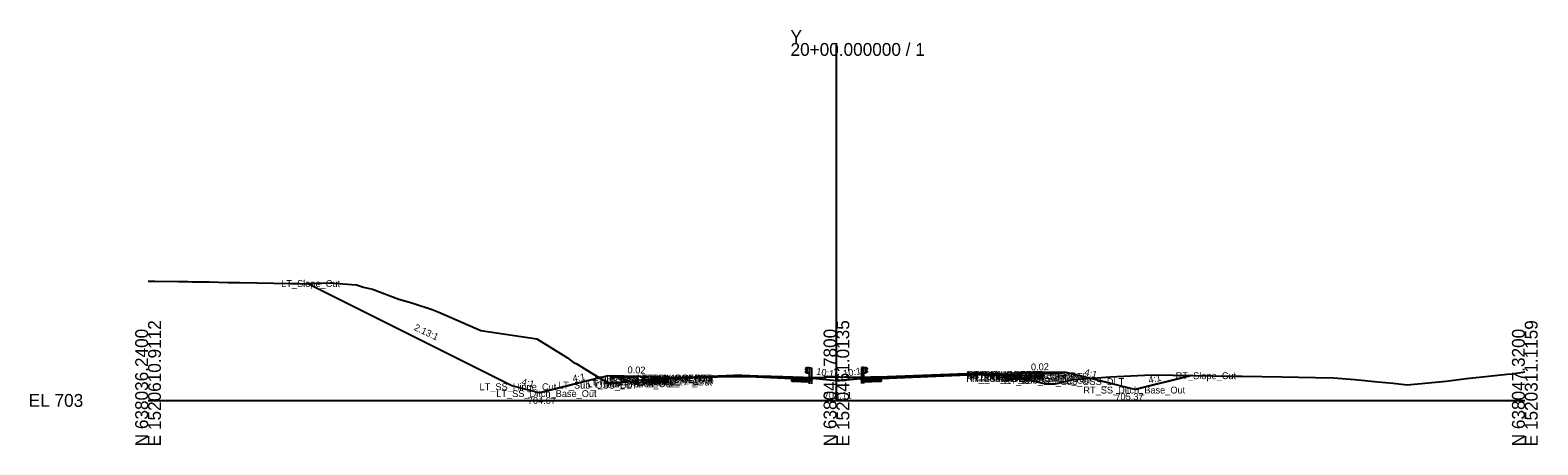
# Model space of a CAD drawing. Extents: x -26 to 303, y -10 to 5039.
# Drawn here: x -25.7 to 302.8, y 3490.3 to 3580.7 of the extents above; entities that cross this region are included whole.
import ezdxf

# ---------------------------------------------------------------- set-up
doc = ezdxf.new("R2010")
doc.units = 0
for name, color, linetype in [('Default', 7, 'Continuous'), ('Exist Cross Section Cell', 7, 'Continuous'), ('Exist XS Center Line Elevation Label', 7, 'Continuous'), ('Exist XS Ground Line', 7, 'Continuous'), ('Prop CMT Pvmt Course 1', 7, 'Continuous'), ('Prop CMT Pvmt Course 2', 7, 'Continuous'), ('Prop CMT Pvmt Course 3', 7, 'Continuous'), ('Prop CMT Pvmt Surface Shoulder', 7, 'Continuous'), ('Prop CMT Shld Paved Course 1', 7, 'Continuous'), ('Prop CMT Shld Paved Course 2', 7, 'Continuous'), ('Prop CMT Shld Paved Course 3', 7, 'Continuous'), ('Prop CMT Slope Grass', 7, 'Continuous'), ('Prop CMT Subgrade Earthwork', 7, 'Continuous'), ('Prop Conc 4in Sidewalk', 7, 'Continuous'), ('Prop XS Ditch Standard Text', 7, 'Continuous'), ('Prop XS Earthwork Shape', 7, 'Continuous'), ('Prop XS Side Slope Text', 7, 'Continuous'), ('Scratch_Level_0', 7, 'Continuous'), ('Typical Curb CELL', 7, 'Continuous'), ('Typical Guardrail CELL', 7, 'Continuous'), ('Typical Shoulder Slope Information CELL', 7, 'Continuous')]:
    doc.layers.add(name, color=color, linetype=linetype)

# ---------------------------------------------------------------- blocks, each defined once
blk = doc.blocks.new('2_6 CURB RIGHT')
at = {"layer": 'Typical Curb CELL'}
for p, q in [((0, -0.58), (0, 0)), ((0, 0), (1.75, -0.07)), ((2, 0.17), (2, 0.18)), ((2.5, 0.42), (2.24, 0.42)), ((2.31, 0.08), (2.33, -0.01)), ((2.46, 0.04), (2.31, 0.08)), ((2.33, -0.01), (2.46, 0.04)), ((2.5, -0.58), (2.5, 0.42)), ((2.5, -0.58), (0, -0.58)), ((0.26, -0.34), (0.35, -0.22)), ((0.38, -0.34), (0.26, -0.34)), ((0.35, -0.22), (0.38, -0.34)), ((1.03, -0.39), (1.09, -0.28)), ((1.19, -0.36), (1.03, -0.39)), ((1.09, -0.28), (1.19, -0.36)), ((1.51, -0.34), (1.6, -0.22)), ((1.63, -0.34), (1.51, -0.34)), ((1.6, -0.22), (1.63, -0.34)), ((2.27, -0.39), (2.34, -0.28)), ((2.44, -0.36), (2.27, -0.39)), ((2.34, -0.28), (2.44, -0.36))]:
    blk.add_line(p, q, dxfattribs=at)
for centre in [(2.27, 0.34), (2.43, 0.12), (2.49, 0.31), (0.01, -0.55), (0.02, -0.25), (0.03, -0.15), (0.07, -0.39), (0.09, -0.18), (0.17, -0.34), (0.2, -0.06), (0.22, -0.58), (0.3, -0.14), (0.34, -0.04), (0.38, -0.51), (0.49, -0.1), (0.52, -0.21), (0.59, -0.53), (0.67, -0.29), (0.69, -0.12), (0.7, -0.45), (0.71, -0.07), (0.76, -0.56), (0.79, -0.26), (0.93, -0.5), (0.97, -0.1), (1.09, -0.15), (1.11, -0.54), (1.26, -0.55), (1.27, -0.25), (1.28, -0.15), (1.32, -0.39), (1.34, -0.18), (1.42, -0.34), (1.45, -0.1), (1.47, -0.58), (1.54, -0.14), (1.63, -0.51), (1.74, -0.1), (1.77, -0.21), (1.84, -0.53), (1.92, -0.29), (1.94, -0.12), (1.95, -0.45), (1.96, -0.07), (2.01, -0.56), (2.04, -0.26), (2.18, -0.5), (2.22, -0.1), (2.34, -0.15), (2.35, -0.54)]:
    blk.add_circle(centre, 0.00802, dxfattribs=at)
for centre, start, end in [((1.76, 0.17), 267.6155, 0), ((2.24, 0.18), 90, 180)]:
    blk.add_arc(centre, 0.24, start, end, dxfattribs=at)

msp = doc.modelspace()

# ---------------------------------------------------------------- linework, layer by layer
at = {"layer": 'Exist Cross Section Cell'}
for p, q in [((150, 3500), (150, 3577.92)), ((0, 3500), (150, 3500)), ((150, 3500), (300, 3500))]:
    msp.add_line(p, q, dxfattribs=at)
at = {"layer": 'Exist XS Ground Line'}
msp.add_lwpolyline([(0, 3525.96), (0.71, 3525.96), (1.5, 3525.97), (6.64, 3525.95), (8.65, 3525.92), (9.66, 3525.87), (12.17, 3525.84), (12.72, 3525.84), (13.29, 3525.83), (17.41, 3525.74), (20.08, 3525.67), (31.09, 3525.46), (31.71, 3525.47), (32.03, 3525.48), (32.73, 3525.47), (34.16, 3525.45), (39.69, 3525.61), (40.1, 3525.62), (40.47, 3525.58), (45.43, 3525.17), (46.93, 3524.72), (48.94, 3524.24), (54.65, 3522.05), (57.49, 3521.25), (61.89, 3519.8), (63.34, 3519.21), (72.53, 3515.25), (84.74, 3513.45), (91.37, 3509.27), (92.73, 3508.27), (93.27, 3508.03), (100.24, 3503.74), (101.36, 3503.75), (101.73, 3503.79), (103.06, 3503.91), (110.58, 3504.76), (111.28, 3504.78), (111.58, 3504.79), (113.51, 3504.85), (114.1, 3504.89), (115.84, 3504.92), (118.35, 3505), (120.85, 3505.08), (121.65, 3505.1), (123.34, 3505.15), (125.84, 3505.22), (128.32, 3505.23), (130.49, 3505.24), (130.82, 3505.24), (132.91, 3505.23), (133.33, 3505.23), (133.78, 3505.23), (135.84, 3505.24), (136.32, 3505.24), (138.34, 3505.24), (142.72, 3505.05), (145, 3504.97), (147.38, 3505.03), (150, 3505.11), (150.67, 3505.13), (152.51, 3505.07), (157.46, 3505.12), (161.91, 3505.12), (162.77, 3505.13), (163.39, 3505.14), (165, 3505.2), (165.89, 3505.23), (166.72, 3505.27), (168.38, 3505.34), (170.18, 3505.41), (170.88, 3505.44), (172.76, 3505.51), (173.37, 3505.53), (173.87, 3505.57), (175.47, 3505.58), (175.86, 3505.59), (177.93, 3505.62), (178.35, 3505.63), (180.54, 3505.66), (181.16, 3505.67), (183.37, 3505.69), (184.8, 3505.69), (185.65, 3505.69), (187.49, 3505.51), (190.17, 3504.92), (195.52, 3503.64), (197.68, 3503.61), (198.38, 3503.75), (201.61, 3504.57), (206.92, 3504.93), (209.58, 3505.14), (217.2, 3505.53), (219.29, 3505.59), (231.77, 3505.35), (235.3, 3505.29), (238.43, 3505.26), (247.06, 3505.15), (254.39, 3505.02), (258.31, 3504.93), (262.96, 3504.54), (267.99, 3504.06), (271.3, 3503.77), (274.37, 3503.4), (282.83, 3504.2), (287.27, 3504.78), (292.12, 3505.28), (296.17, 3505.7), (297.31, 3505.81), (300, 3506.22)], dxfattribs=at)
at = {"layer": 'Prop CMT Pvmt Course 1'}
for points in [[(186.74, 3505.38), (186.74, 3505.63)], [(113.24, 3504.85), (113.24, 3504.6)], [(113.24, 3504.6), (113.25, 3504.6)], [(113.25, 3504.6), (113.25, 3504.85)], [(140.25, 3504.81), (140.25, 3505.06)], [(159.75, 3504.81), (159.75, 3505.06)]]:
    msp.add_lwpolyline(points, dxfattribs=at)
at = {"layer": 'Prop CMT Pvmt Course 2'}
for points in [[(113.25, 3504.6), (113.24, 3504.6)], [(113.24, 3504.6), (113.24, 3504.35)], [(113.24, 3504.35), (113.25, 3504.35)], [(113.25, 3504.35), (113.25, 3504.6)], [(140.25, 3504.56), (140.25, 3504.81)], [(159.75, 3504.56), (159.75, 3504.81)]]:
    msp.add_lwpolyline(points, dxfattribs=at)
at = {"layer": 'Prop CMT Pvmt Course 3'}
for points in [[(113.25, 3504.35), (113.24, 3504.35)], [(113.24, 3504.35), (113.24, 3503.98)], [(113.24, 3503.98), (113.25, 3503.98)], [(113.25, 3503.98), (113.25, 3504.35)], [(140.25, 3504.19), (140.25, 3504.56)], [(140.26, 3504.19), (140.25, 3504.19)], [(159.74, 3504.19), (159.75, 3504.19)], [(159.75, 3504.19), (159.75, 3504.56)]]:
    msp.add_lwpolyline(points, dxfattribs=at)
at = {"layer": 'Prop CMT Pvmt Surface Shoulder'}
for points in [[(129.39, 3505.5), (112.24, 3504.81)], [(129.39, 3505.5), (143.25, 3504.94)], [(180.3, 3505.88), (156.75, 3504.94)], [(180.3, 3505.88), (187.75, 3505.59)]]:
    msp.add_lwpolyline(points, dxfattribs=at)
at = {"layer": 'Prop CMT Shld Paved Course 1'}
for p, q in [((176.3, 3505.79), (187.74, 3505.34)), ((129.39, 3505.25), (113.25, 3504.6)), ((129.39, 3505.25), (140.25, 3504.81))]:
    msp.add_line(p, q, dxfattribs=at)
for points in [[(159.77, 3504.81), (180.3, 3505.63)], [(112.24, 3504.56), (113.25, 3504.6)], [(113.24, 3504.6), (113.24, 3504.85)], [(187.75, 3505.34), (186.74, 3505.38)]]:
    msp.add_lwpolyline(points, dxfattribs=at)
at = {"layer": 'Prop CMT Shld Paved Course 2'}
for p, q in [((143.77, 3504.42), (143.51, 3504.68)), ((156.23, 3504.42), (156.49, 3504.68))]:
    msp.add_line(p, q, dxfattribs=at)
for points in [[(113.25, 3504.6), (112.24, 3504.56)], [(112.24, 3504.31), (113.25, 3504.35)], [(113.24, 3504.35), (113.24, 3504.6)], [(140.25, 3504.81), (143.51, 3504.68)], [(143.77, 3504.42), (140.25, 3504.56)], [(156.23, 3504.42), (159.75, 3504.56)], [(159.75, 3504.81), (156.49, 3504.68)], [(186.74, 3505.38), (187.75, 3505.34)], [(187.75, 3505.09), (186.74, 3505.13)]]:
    msp.add_lwpolyline(points, dxfattribs=at)
at = {"layer": 'Prop CMT Shld Paved Course 3'}
for p, q in [((109.24, 3504.23), (108.81, 3503.8)), ((109.74, 3504.23), (109.24, 3504.23)), ((144.16, 3504.03), (143.77, 3504.42)), ((155.84, 3504.03), (156.23, 3504.42)), ((190.25, 3505), (190.75, 3505)), ((190.75, 3505), (191.18, 3504.57))]:
    msp.add_line(p, q, dxfattribs=at)
for points in [[(108.81, 3503.8), (113.25, 3503.98)], [(113.25, 3504.35), (112.24, 3504.31)], [(113.24, 3503.98), (113.24, 3504.35)], [(140.25, 3504.56), (143.77, 3504.42)], [(144.16, 3504.03), (140.25, 3504.19)], [(155.84, 3504.03), (159.75, 3504.19)], [(159.75, 3504.56), (156.23, 3504.42)], [(186.74, 3505.13), (187.75, 3505.09)], [(191.18, 3504.57), (186.74, 3504.75)]]:
    msp.add_lwpolyline(points, dxfattribs=at)
at = {"layer": 'Prop CMT Slope Grass'}
for p, q in [((199.75, 3506.19), (190.25, 3506)), ((215.03, 3502.37), (199.75, 3506.19)), ((85.24, 3501.67), (100.24, 3505.42)), ((100.24, 3505.42), (109.74, 3505.23)), ((150, 3504.27), (143.25, 3504.94)), ((150, 3504.27), (156.75, 3504.94)), ((215.03, 3502.37), (227.29, 3505.44))]:
    msp.add_line(p, q, dxfattribs=at)
msp.add_lwpolyline([(85.24, 3501.67), (79.24, 3503.17), (34.65, 3525.46)], dxfattribs=at)
at = {"layer": 'Prop CMT Subgrade Earthwork'}
for p, q in [((186.74, 3504.75), (186.74, 3505.63)), ((187.75, 3505), (187.75, 3505.59)), ((190.25, 3506), (190.25, 3505)), ((191.18, 3504.57), (192.65, 3506.05)), ((108.81, 3503.8), (107.34, 3505.27)), ((109.74, 3505.23), (109.74, 3504.23)), ((109.74, 3504.23), (112.24, 3504.23)), ((112.24, 3504.23), (112.24, 3504.81)), ((113.25, 3503.98), (113.25, 3504.85)), ((140.25, 3505.06), (140.25, 3504.19)), ((159.75, 3505.06), (159.75, 3504.19)), ((190.25, 3505), (187.75, 3505))]:
    msp.add_line(p, q, dxfattribs=at)
for points in [[(113.25, 3503.98), (108.81, 3503.8)], [(140.25, 3505.06), (140.25, 3504.19), (140.26, 3504.19)], [(140.25, 3504.19), (144.16, 3504.03)], [(144.16, 3504.03), (144.91, 3504.78)], [(155.84, 3504.03), (155.09, 3504.78)], [(159.75, 3504.19), (155.84, 3504.03)], [(159.75, 3505.06), (159.75, 3504.19), (159.74, 3504.19)], [(186.74, 3504.75), (191.18, 3504.57)]]:
    msp.add_lwpolyline(points, dxfattribs=at)
at = {"layer": 'Prop Conc 4in Sidewalk'}
for p, q in [((194.25, 3506.08), (194.25, 3505.75)), ((199.25, 3505.85), (194.25, 3505.75)), ((199.25, 3506.18), (199.25, 3505.85)), ((100.74, 3505.41), (100.74, 3505.07)), ((100.74, 3505.07), (105.74, 3504.97)), ((105.74, 3505.31), (105.74, 3504.97))]:
    msp.add_line(p, q, dxfattribs=at)
at = {"layer": 'Prop XS Earthwork Shape'}
for points in [[(40.1, 3525.62), (40.47, 3525.58), (45.43, 3525.17), (46.93, 3524.72), (48.94, 3524.24), (54.65, 3522.05), (57.49, 3521.25), (61.89, 3519.8), (63.34, 3519.21), (72.53, 3515.25), (84.74, 3513.45), (91.37, 3509.27), (92.73, 3508.27), (93.27, 3508.03), (98.3, 3504.93), (85.24, 3501.67), (79.24, 3503.17), (34.65, 3525.46), (39.69, 3525.61)], [(129.39, 3505.5), (135.81, 3505.24), (133.78, 3505.23), (133.33, 3505.23), (132.91, 3505.23), (130.82, 3505.24), (130.49, 3505.24), (128.32, 3505.23), (125.84, 3505.22), (123.34, 3505.15), (121.65, 3505.1), (120.85, 3505.08), (118.35, 3505), (115.84, 3504.92), (114.16, 3504.89)], [(183.37, 3505.69), (184.8, 3505.69), (185.2, 3505.69), (180.3, 3505.88), (161.15, 3505.12), (161.91, 3505.12), (162.77, 3505.13), (163.39, 3505.14), (165, 3505.2), (165.89, 3505.23), (166.72, 3505.27), (168.38, 3505.34), (170.18, 3505.41), (170.88, 3505.44), (172.76, 3505.51), (173.37, 3505.53), (173.87, 3505.57), (175.47, 3505.58), (175.86, 3505.59), (177.93, 3505.62), (178.35, 3505.63), (180.54, 3505.66), (181.16, 3505.67)], [(185.65, 3505.69), (186, 3505.66), (185.2, 3505.69)], [(186.74, 3505.59), (186.74, 3505.63), (186, 3505.66)], [(186.74, 3505.59), (187.49, 3505.51), (187.75, 3505.46), (187.75, 3505), (189.81, 3505), (190.17, 3504.92), (191.26, 3504.66), (191.18, 3504.57), (186.74, 3504.75)], [(187.75, 3505.46), (189.81, 3505), (187.75, 3505)], [(191.26, 3504.66), (195.52, 3503.64), (197.68, 3503.61), (198.38, 3503.75), (201.61, 3504.57), (205.25, 3504.82), (199.75, 3506.19), (192.65, 3506.05)], [(219.29, 3505.59), (227.29, 3505.44), (215.03, 3502.37), (205.25, 3504.82), (206.92, 3504.93), (209.58, 3505.14), (217.2, 3505.53)], [(98.3, 3504.93), (100.24, 3505.42), (107.33, 3505.27), (108.13, 3504.48), (103.06, 3503.91), (101.73, 3503.79), (101.36, 3503.75), (100.24, 3503.74)], [(109.74, 3504.23), (112.24, 3504.23), (112.24, 3504.81), (113.25, 3504.85), (113.25, 3503.98), (108.81, 3503.8), (108.13, 3504.48), (109.74, 3504.66)], [(109.74, 3504.66), (110.58, 3504.76), (111.28, 3504.78), (111.58, 3504.79), (112.24, 3504.81), (112.24, 3504.23), (109.74, 3504.23)], [(113.51, 3504.85), (114.01, 3504.88), (113.25, 3504.85)], [(114.1, 3504.89), (114.16, 3504.89), (114.01, 3504.88)], [(150.67, 3505.13), (152.51, 3505.07), (157.46, 3505.12), (161.15, 3505.12), (159.75, 3505.06), (156.75, 3504.94), (155.09, 3504.78), (150, 3504.27), (144.91, 3504.78), (143.25, 3504.94), (140.25, 3505.06), (135.81, 3505.24), (135.84, 3505.24), (136.32, 3505.24), (138.34, 3505.24), (142.72, 3505.05), (145, 3504.97), (147.38, 3505.03), (150, 3505.11)], [(140.25, 3505.06), (143.25, 3504.94), (144.91, 3504.78), (144.16, 3504.03), (140.26, 3504.19)], [(159.74, 3504.19), (155.84, 3504.03), (155.09, 3504.78), (156.75, 3504.94), (159.75, 3505.06)]]:
    msp.add_lwpolyline(points, close=True, dxfattribs=at)
at = {"layer": 'Typical Guardrail CELL'}
for p, q in [((143.57, 3507.13), (143.28, 3506.93)), ((143.57, 3506.6), (143.28, 3506.8)), ((143.57, 3506.5), (143.28, 3506.3)), ((143.57, 3505.97), (143.28, 3506.17)), ((144.07, 3507.13), (143.57, 3507.13)), ((143.57, 3507.13), (143.57, 3505.97)), ((143.57, 3506.55), (143.57, 3506.6)), ((143.57, 3506.55), (143.57, 3506.5)), ((144.07, 3505.97), (143.57, 3505.97)), ((144.07, 3507.13), (144.07, 3504.64)), ((144.07, 3507.13), (144.57, 3507.13)), ((144.57, 3507.13), (144.57, 3504.64)), ((155.93, 3507.17), (155.43, 3507.17)), ((155.43, 3507.17), (155.43, 3504.68)), ((155.93, 3507.17), (155.93, 3504.68)), ((155.93, 3507.17), (156.43, 3507.17)), ((155.93, 3506.01), (156.43, 3506.01)), ((156.43, 3507.17), (156.43, 3506.01)), ((156.43, 3507.17), (156.72, 3506.96)), ((156.43, 3506.63), (156.72, 3506.84)), ((156.43, 3506.59), (156.43, 3506.63)), ((156.43, 3506.59), (156.43, 3506.54)), ((156.43, 3506.54), (156.72, 3506.34)), ((156.43, 3506.01), (156.72, 3506.21)), ((144.07, 3504.64), (144.57, 3504.64)), ((144.07, 3504.64), (144.07, 3503.63)), ((144.57, 3504.64), (144.57, 3503.63)), ((155.93, 3504.68), (155.43, 3504.68)), ((155.43, 3504.68), (155.43, 3503.67)), ((155.93, 3504.68), (155.93, 3503.67))]:
    msp.add_line(p, q, dxfattribs=at)
for centre, start, end in [((143.33, 3506.86), 125.003, 235.0112), ((143.33, 3506.24), 125.0059, 235.0366), ((156.67, 3506.9), 304.9888, 54.997), ((156.67, 3506.27), 304.9634, 54.9941)]:
    msp.add_arc(centre, 0.0776, start, end, dxfattribs=at)

# ---------------------------------------------------------------- block references
at = {"layer": 'Prop CMT Slope Grass'}
msp.add_blockref('2_6 CURB RIGHT', (187.75, 3505.59), dxfattribs=at)
at = {"layer": 'Prop CMT Slope Grass', "yscale": -1, "rotation": 180}
msp.add_blockref('2_6 CURB RIGHT', (112.24, 3504.81), dxfattribs=at)

# ---------------------------------------------------------------- texts
at = {"layer": 'Default'}
msp.add_text('-', height=0.0001, dxfattribs=at).set_placement((0, 3500))
at = {"layer": 'Exist Cross Section Cell'}
for s, p in [('Y', (140, 3577.92)), ('20+00.000000 / 1', (140, 3575.12)), ('EL 703', (-26, 3498.6))]:
    msp.add_text(s, height=2.8, dxfattribs=at).set_placement(p)
for s, p in [('N 638036.2400', (0, 3490)), ('E 1520610.9112', (2.8, 3490)), ('N 638041.7800', (150, 3490)), ('E 1520461.0135', (152.8, 3490)), ('N 638047.3200', (300, 3490)), ('E 1520311.1159', (302.8, 3490))]:
    msp.add_text(s, height=2.8, rotation=90, dxfattribs=at).set_placement(p)
at = {"layer": 'Exist XS Center Line Elevation Label'}
msp.add_text('708.11', height=1.5, dxfattribs=at).set_placement((147.24, 3500.36))
at = {"layer": 'Prop XS Ditch Standard Text'}
for s, p in [('704.67', (82.75, 3499.23)), ('705.37', (210.79, 3500.08))]:
    msp.add_text(s, height=1.5, dxfattribs=at).set_placement(p)
at = {"layer": 'Prop XS Side Slope Text'}
for s, rotation, p in [('2.13:1', 334.7993, (57.81, 3515.4)), ('4:1', 9.4623, (92.62, 3503.99)), ('10:1', 350.5377, (145.51, 3505.64)), ('10:1', 9.4623, (151.61, 3505.1)), ('4:1', 346.7942, (203.91, 3505.49)), ('4:1', 13.2058, (218.16, 3503.67)), ('4:1', 345.9638, (81.27, 3503.43))]:
    msp.add_text(s, height=1.5, rotation=rotation, dxfattribs=at).set_placement(p)
at = {"layer": 'Scratch_Level_0'}
for s, p in [('LT_Slope_Cut', (29.01, 3524.72)), ('LT_Sub_Out_DLT', (106.49, 3504.13)), ('LT_PV1_PGL_Out', (106.54, 3504.13)), ('LT_PV1_OEOT', (107.79, 3504.13)), ('RT_PV2_PGL_Out', (178.27, 3504.66)), ('RT_PV3_PGL_Out', (178.27, 3504.41)), ('RT_Sub_PGL_Out', (178.31, 3504.03)), ('RT_Sub_Out_DLT', (178.37, 3504.91)), ('RT_PV1_PGL_Out', (178.45, 3504.91)), ('RT_PV2_OEOT', (179.54, 3504.66)), ('RT_PV3_OEOT', (179.54, 3504.41)), ('RT_Sub_OEOT', (179.57, 3504.03)), ('RT_PV1_OEOT', (179.72, 3504.91)), ('RT_PS3_Shelf_Out', (186.93, 3504.04)), ('RT_PS1_OEOP', (187.78, 3504.59)), ('RT_PS2_OEOP', (187.86, 3504.32)), ('RT_PS3_OEOP', (188.12, 3504.06)), ('RT_GS_OS_CTL', (189.12, 3504.51)), ('RT_Slope_Cut', (223.93, 3504.63)), ('LT_SS_Hinge_Cut', (72.23, 3502.23)), ('LT_SS_Ditch_Base_Out', (75.88, 3500.73)), ('LT_Sub_OSS_DLT', (89.35, 3502.58)), ('LT_Sub_Trench_Out', (95.74, 3502.88)), ('LT_PS3_Shelf_Out', (96.95, 3503.27)), ('LT_GS_OS_CTL', (97.19, 3503.73)), ('LT_PS3_OEOP', (99.15, 3503.29)), ('LT_PS2_OEOP', (99.41, 3503.55)), ('LT_PS1_OEOP', (99.85, 3503.81)), ('LT_PV2_PGL_Out', (106.36, 3503.88)), ('LT_PV3_PGL_Out', (106.36, 3503.63)), ('LT_Sub_PGL_Out', (106.4, 3503.26)), ('LT_PV2_OEOT', (107.61, 3503.88)), ('LT_PV3_OEOT', (107.61, 3503.63)), ('LT_Sub_OEOT', (107.64, 3503.26)), ('RT_Sub_Trench_Out', (186.5, 3503.65)), ('RT_Sub_OSS_DLT', (195.1, 3503.35)), ('RT_SS_Ditch_Base_Out', (203.81, 3501.51))]:
    msp.add_text(s, height=1.5, dxfattribs=at).set_placement(p)
at = {"layer": 'Typical Shoulder Slope Information CELL'}
for rotation, p in [(358.8597, (104.47, 3505.92)), (1.1403, (192.4, 3506.53))]:
    msp.add_text('0.02', height=1.5, rotation=rotation, dxfattribs=at).set_placement(p)

doc.saveas('drawing.dxf')
